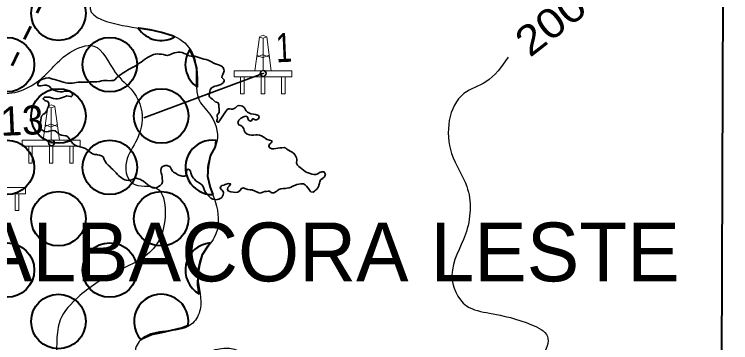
# Model space of a CAD drawing. Extents: x -10.5 to 30.8, y 18.4 to 58.7.
# Drawn here: x 25.827 to 30.756, y 40.973 to 43.233 of the extents above; entities that cross this region are included whole.
import ezdxf
from ezdxf.enums import TextEntityAlignment as Align

# ---------------------------------------------------------------- set-up
doc = ezdxf.new("R2010")
doc.units = 0
doc.header["$LTSCALE"] = 0.08
doc.header["$PDMODE"] = 32
doc.header["$PDSIZE"] = 0.04
doc.linetypes.add('DASH_DOUBLE_DOT', pattern=[9.2, 5, -1.2, 0.3, -1.2, 0.3, -1.2])
doc.layers.add('13', color=7, linetype='Continuous')
for name, color, linetype, lineweight in [('19', 7, 'DASH_DOUBLE_DOT', 53), ('28', 7, 'Continuous', 25), ('36', 7, 'Continuous', 13), ('44', 7, 'Continuous', 35), ('6', 7, 'Continuous', 40), ('60', 7, 'Continuous', 13), ('8', 7, 'Continuous', 25)]:
    doc.layers.add(name, color=color, linetype=linetype, lineweight=lineweight)

msp = doc.modelspace()

# ---------------------------------------------------------------- linework, layer by layer
at = {"layer": '19'}
msp.add_arc((-10.0428, 60.19451), 39.81815, 297.24377, 345.91847, dxfattribs=at)
at = {"layer": '28', "lineweight": 35}
for points in [[(27.09656, 42.93611), (27.08285, 42.94108), (27.06886, 42.9447), (27.05912, 42.94579), (27.0445, 42.94634), (27.03016, 42.94842), (27.02726, 42.94931), (27.01385, 42.95514), (27.00867, 42.95795), (26.99573, 42.96464), (26.98227, 42.96979), (26.968, 42.97204), (26.95325, 42.97191), (26.94302, 42.97062), (26.92882, 42.96748), (26.92765, 42.96709), (26.91402, 42.96246), (26.90053, 42.95664), (26.8934, 42.9538), (26.87937, 42.9505), (26.86785, 42.95169), (26.85343, 42.95562), (26.85325, 42.95578), (26.83888, 42.95853), (26.82441, 42.95976), (26.81325, 42.96046), (26.79877, 42.95983), (26.79752, 42.95961), (26.78341, 42.95613), (26.76981, 42.95082), (26.75678, 42.94402), (26.7478, 42.93908), (26.73548, 42.93146), (26.72335, 42.92334), (26.7218, 42.92227), (26.71003, 42.91366), (26.69834, 42.90506), (26.68665, 42.89646), (26.67461, 42.88818), (26.66936, 42.88475), (26.65705, 42.87696), (26.64455, 42.86967), (26.64289, 42.86893), (26.63013, 42.8618), (26.61736, 42.85484), (26.60468, 42.84788), (26.59209, 42.84059), (26.57978, 42.8328), (26.56863, 42.82524), (26.55694, 42.81681), (26.55302, 42.81377), (26.54168, 42.80501), (26.53071, 42.79543), (26.51976, 42.78534), (26.50947, 42.77748), (26.49559, 42.77688), (26.49466, 42.77684), (26.48008, 42.77654), (26.46566, 42.7766), (26.45871, 42.77748), (26.44414, 42.77887), (26.44254, 42.7788), (26.42824, 42.77599), (26.42625, 42.7754), (26.41252, 42.77109)], [(27.22661, 42.54589), (27.23642, 42.55677), (27.23711, 42.56422), (27.23684, 42.57062), (27.23664, 42.57331), (27.23508, 42.58774), (27.23494, 42.58909), (27.23439, 42.60374), (27.23436, 42.61031), (27.23032, 42.6238), (27.21734, 42.62762), (27.20862, 42.63028), (27.19856, 42.64047), (27.19072, 42.6484), (27.17855, 42.65681), (27.16854, 42.66599), (27.16826, 42.67239), (27.16833, 42.67475), (27.16913, 42.68929), (27.17121, 42.70355), (27.17496, 42.71434), (27.18312, 42.7265), (27.18759, 42.7304), (27.20081, 42.73671), (27.20556, 42.73809), (27.21977, 42.7409), (27.23378, 42.74471), (27.24727, 42.75052), (27.25361, 42.754), (27.26486, 42.76309), (27.27075, 42.77515), (27.27043, 42.78256), (27.26477, 42.78856), (27.25375, 42.79769), (27.25748, 42.81084), (27.2614, 42.81961), (27.26617, 42.83028), (27.26986, 42.84443), (27.26935, 42.85419), (27.26354, 42.86777), (27.25947, 42.87198), (27.24691, 42.8797), (27.23773, 42.88335), (27.22381, 42.88747), (27.2102, 42.89211), (27.20831, 42.89288), (27.19536, 42.89974), (27.18274, 42.90695), (27.17403, 42.9113), (27.16064, 42.91679), (27.14678, 42.92142), (27.14559, 42.9217), (27.13151, 42.92548), (27.11751, 42.92926), (27.10358, 42.93355), (27.09656, 42.93611)], [(26.41252, 42.77109), (26.40918, 42.77027), (26.39482, 42.76881), (26.38015, 42.76868), (26.36546, 42.76906), (26.36403, 42.769), (26.34956, 42.76837), (26.34888, 42.76834), (26.33442, 42.76738), (26.31986, 42.76675), (26.30538, 42.76612), (26.2908, 42.76583), (26.28035, 42.76571), (26.26577, 42.76542), (26.25132, 42.76412), (26.24178, 42.76253), (26.22747, 42.75988), (26.21304, 42.75825), (26.20866, 42.75823), (26.1941, 42.75929), (26.17982, 42.76204), (26.17615, 42.76306), (26.16223, 42.76701), (26.14838, 42.77148), (26.14804, 42.77146), (26.13411, 42.77575), (26.12019, 42.7797), (26.1062, 42.78348), (26.10586, 42.78347), (26.09178, 42.78724), (26.07801, 42.79188), (26.06713, 42.79562), (26.06146, 42.79622), (26.04685, 42.79474), (26.04385, 42.79394), (26.03003, 42.7898), (26.01988, 42.78649), (26.00691, 42.7802), (26.00195, 42.77611), (25.99257, 42.76474), (25.98673, 42.7515), (25.9925, 42.74112), (26.00108, 42.74149), (26.00748, 42.74177), (26.00798, 42.74179), (26.02229, 42.74443), (26.03329, 42.74558), (26.04792, 42.7447), (26.05276, 42.7439), (26.06629, 42.73908), (26.06908, 42.73684), (26.07876, 42.72562), (26.08376, 42.72112), (26.09632, 42.71357), (26.09941, 42.71218), (26.11289, 42.70669)], [(26.11289, 42.70669), (26.12675, 42.70206), (26.12974, 42.70118), (26.14394, 42.69859), (26.15787, 42.7002), (26.16683, 42.7016), (26.18126, 42.70341), (26.18821, 42.70455), (26.20255, 42.70433), (26.21348, 42.6994), (26.22458, 42.69027), (26.22476, 42.68994), (26.22632, 42.67534), (26.22029, 42.66664), (26.21169, 42.66846), (26.19873, 42.66993), (26.18904, 42.6717), (26.18268, 42.67041), (26.17218, 42.66557), (26.17103, 42.66502), (26.15751, 42.65971), (26.15202, 42.65795), (26.13803, 42.65398), (26.12361, 42.65183), (26.11115, 42.65146), (26.0968, 42.65371), (26.09611, 42.65402), (26.08238, 42.6595), (26.06864, 42.66329), (26.06281, 42.66354), (26.04831, 42.66342), (26.0478, 42.66357), (26.03328, 42.66395), (26.02415, 42.65276), (26.03082, 42.64664), (26.03526, 42.6416), (26.03613, 42.6408), (26.04955, 42.6348), (26.05929, 42.63185), (26.06514, 42.61945), (26.06464, 42.60762), (26.06297, 42.60334), (26.0568, 42.59008), (26.05599, 42.58718), (26.05315, 42.57289), (26.05126, 42.56792), (26.04222, 42.55656), (26.03545, 42.55121), (26.02351, 42.54277), (26.0231, 42.54241), (26.01336, 42.5317), (26.01025, 42.52178), (26.00912, 42.50689), (26.00874, 42.50401), (26.00657, 42.48975), (26.00398, 42.47564), (26.00309, 42.46683), (26.00288, 42.45231), (26.00288, 42.45231), (26.00636, 42.44589), (26.01207, 42.43871), (26.01747, 42.43675), (26.01961, 42.43583), (26.03169, 42.42775), (26.03254, 42.42745)], [(27.34897, 42.59081), (27.34953, 42.59134), (27.34317, 42.58635), (27.33405, 42.58275), (27.32757, 42.58044), (27.31966, 42.5801), (27.30953, 42.58236), (27.301, 42.58267), (27.292, 42.57823), (27.2863, 42.57141), (27.28006, 42.56186), (27.2701, 42.54827), (27.25774, 42.52801), (27.23924, 42.49938), (27.23044, 42.49039), (27.23213, 42.4903), (27.23019, 42.49021), (27.21978, 42.49516), (27.2195, 42.50156), (27.22123, 42.51024), (27.22414, 42.51896), (27.22145, 42.53251), (27.22213, 42.54013), (27.22661, 42.54589)], [(27.5998, 42.35997), (27.59789, 42.36309), (27.58242, 42.36782), (27.58183, 42.36796), (27.56729, 42.37256), (27.5552, 42.37929), (27.55137, 42.38199), (27.53938, 42.39008), (27.52658, 42.39745), (27.5138, 42.40246), (27.49953, 42.40471), (27.48741, 42.40419), (27.47289, 42.40255), (27.45849, 42.4021), (27.44391, 42.40383), (27.4299, 42.40811), (27.42576, 42.41013), (27.41449, 42.41925), (27.40978, 42.42866), (27.40882, 42.43149), (27.40484, 42.44548), (27.39736, 42.45848), (27.38569, 42.46709), (27.38534, 42.46724), (27.37149, 42.4717), (27.37053, 42.4725), (27.36356, 42.48536), (27.36357, 42.48721), (27.36931, 42.50062), (27.37217, 42.50462), (27.38252, 42.51502), (27.38759, 42.51861), (27.40374, 42.5274), (27.41951, 42.53129), (27.43008, 42.52669), (27.4309, 42.52537), (27.43507, 42.51088), (27.43827, 42.50512), (27.45065, 42.49772), (27.45998, 42.50235), (27.46586, 42.51441), (27.46948, 42.51473), (27.48437, 42.50779), (27.4936, 42.50683), (27.50662, 42.51398), (27.50678, 42.51415), (27.51132, 42.52801), (27.50565, 42.53637), (27.50026, 42.54001), (27.4865, 42.54431), (27.47159, 42.54586), (27.45706, 42.54826), (27.45408, 42.54898), (27.44067, 42.55498), (27.43214, 42.55899), (27.42088, 42.56795), (27.41666, 42.57569), (27.41036, 42.58892), (27.40805, 42.59151), (27.39597, 42.59993), (27.38728, 42.60394), (27.37326, 42.60637), (27.36179, 42.6025), (27.35032, 42.59273), (27.34897, 42.59081)], [(26.03254, 42.42745), (26.04657, 42.42486), (26.06165, 42.42703), (26.06675, 42.42826), (26.08075, 42.43207), (26.09135, 42.43455), (26.09228, 42.43459), (26.10643, 42.43099), (26.10772, 42.43037), (26.11964, 42.42195), (26.12682, 42.41585), (26.1386, 42.40674), (26.15159, 42.40089), (26.16506, 42.39945), (26.17947, 42.39772), (26.1828, 42.39668), (26.19494, 42.38894), (26.20496, 42.37757), (26.21193, 42.36674), (26.21978, 42.35476), (26.22934, 42.34421), (26.24111, 42.33528), (26.25406, 42.32842), (26.25843, 42.32675), (26.27244, 42.32263), (26.28659, 42.3192), (26.29564, 42.31672), (26.30935, 42.31158), (26.31572, 42.30865), (26.32834, 42.30144), (26.34011, 42.29267), (26.34046, 42.29235), (26.35158, 42.28288), (26.36333, 42.27445), (26.36488, 42.27367), (26.37859, 42.2687), (26.39147, 42.26723), (26.39878, 42.26586), (26.41309, 42.2626), (26.42613, 42.25945), (26.43809, 42.25204), (26.44044, 42.24827), (26.44527, 42.23414), (26.4467, 42.23032), (26.45324, 42.21745), (26.46185, 42.20568), (26.47184, 42.19498), (26.48273, 42.18499), (26.49386, 42.17519), (26.50492, 42.16521), (26.5065, 42.16376), (26.51666, 42.15307), (26.52656, 42.14253), (26.53648, 42.13166), (26.54662, 42.12147), (26.5574, 42.11199)], [(27.92664, 42.07186), (27.92838, 42.08054), (27.93422, 42.09361), (27.93649, 42.09573), (27.94879, 42.10385), (27.94985, 42.10458), (27.96003, 42.11497), (27.96241, 42.11844), (27.9667, 42.13229), (27.96612, 42.13598), (27.95751, 42.14792), (27.95673, 42.14839), (27.94266, 42.15014), (27.92772, 42.1446), (27.92723, 42.14424), (27.91425, 42.13626), (27.90159, 42.13049), (27.88953, 42.13047), (27.87473, 42.13354), (27.86261, 42.1369), (27.84884, 42.14136), (27.83569, 42.14703), (27.82757, 42.15157), (27.81557, 42.15982), (27.80396, 42.16894), (27.7926, 42.17823), (27.7848, 42.18497), (27.77481, 42.19567), (27.76887, 42.20807), (27.7685, 42.21277), (27.77015, 42.22735), (27.77015, 42.23325), (27.76716, 42.24763), (27.76611, 42.25045), (27.7593, 42.26365), (27.75002, 42.27539), (27.73883, 42.28469), (27.73838, 42.28517), (27.72568, 42.29221), (27.71259, 42.29856), (27.70272, 42.30455), (27.6949, 42.3118), (27.68335, 42.31551), (27.66803, 42.31485), (27.65427, 42.31341), (27.64, 42.31178), (27.62558, 42.30981), (27.61292, 42.30808), (27.59774, 42.3081), (27.58478, 42.31328), (27.57792, 42.32377), (27.57771, 42.32478), (27.58157, 42.33894), (27.59185, 42.34681), (27.59697, 42.35125), (27.5998, 42.35997)], [(26.5574, 42.11199), (26.56071, 42.10943), (26.57295, 42.10136), (26.58605, 42.09501), (26.5975, 42.09146), (26.61191, 42.08972), (26.61217, 42.08973), (26.6266, 42.09137), (26.64047, 42.09635), (26.64516, 42.09892), (26.65824, 42.10454), (26.66531, 42.10485), (26.67989, 42.10126), (26.68915, 42.09778), (26.70247, 42.09195), (26.71477, 42.08455), (26.71807, 42.08217), (26.72928, 42.0727), (26.74031, 42.06323), (26.74625, 42.05859), (26.75816, 42.05034), (26.77111, 42.04331), (26.77963, 42.03929), (26.79383, 42.0367), (26.80253, 42.03843), (26.81589, 42.04524), (26.8191, 42.04707), (26.83121, 42.05569), (26.84061, 42.06655), (26.84544, 42.07958), (26.84595, 42.08736), (26.84447, 42.10197), (26.84318, 42.11423), (26.84113, 42.12847), (26.8377, 42.14165), (26.83463, 42.15602), (26.83435, 42.15871), (26.836, 42.17312), (26.83669, 42.17466), (26.84678, 42.18522), (26.86093, 42.1914), (26.86453, 42.19206), (26.87903, 42.19218), (26.88328, 42.19135), (26.89644, 42.18534), (26.90143, 42.17915), (26.90768, 42.16542), (26.91496, 42.15309), (26.9228, 42.14719), (26.93585, 42.13999), (26.94682, 42.13187), (26.95259, 42.12908), (26.96646, 42.12428), (26.96774, 42.124), (26.98159, 42.11954), (26.98507, 42.11901), (26.99978, 42.12032), (27.00918, 42.12512), (27.01083, 42.12806), (27.0116, 42.14327), (27.0122, 42.15291), (27.01488, 42.165), (27.02333, 42.1684), (27.03214, 42.16355), (27.03783, 42.153)], [(27.03783, 42.153), (27.0411, 42.14168), (27.04542, 42.1277), (27.05146, 42.11666), (27.06023, 42.10489), (27.06539, 42.09871), (27.07555, 42.08818), (27.08706, 42.07924), (27.09337, 42.0758), (27.10649, 42.06878), (27.11781, 42.06049), (27.11781, 42.06049), (27.12533, 42.04851), (27.1304, 42.03473), (27.13557, 42.02045), (27.14235, 42.00792), (27.15087, 41.99615), (27.16062, 41.98527), (27.16626, 41.97961), (27.17722, 41.96996), (27.17973, 41.96839), (27.19261, 41.96118), (27.20669, 41.95741), (27.20812, 41.9573), (27.22276, 41.9581), (27.23367, 41.96127), (27.24689, 41.96775), (27.2542, 41.97228), (27.25724, 41.97595), (27.26306, 41.9897), (27.26335, 41.99072), (27.26662, 42.00469), (27.26597, 42.01006), (27.25733, 42.02268), (27.25055, 42.02744), (27.24283, 42.03807), (27.24577, 42.04242), (27.25284, 42.05234), (27.25547, 42.05397), (27.2697, 42.05829), (27.27162, 42.05888), (27.28446, 42.06416), (27.29921, 42.06834), (27.30005, 42.06838), (27.31433, 42.06562), (27.31453, 42.0631), (27.30421, 42.05017), (27.29637, 42.04039), (27.29348, 42.02728), (27.30147, 42.01598), (27.30173, 42.01583), (27.31551, 42.01119), (27.31923, 42.01085), (27.33378, 42.00996), (27.33471, 42.00983), (27.35018, 42.00696)], [(27.35018, 42.00696), (27.36376, 42.0089), (27.37311, 42.01706), (27.38353, 42.02375), (27.38833, 42.03357), (27.38978, 42.03515), (27.40422, 42.03864), (27.41291, 42.03463), (27.41936, 42.03171), (27.43351, 42.0281), (27.43589, 42.0277), (27.45047, 42.02614), (27.46464, 42.02405), (27.46609, 42.02361), (27.47953, 42.01913), (27.49305, 42.01246), (27.49556, 42.01105), (27.5096, 42.00424), (27.52331, 42.00315), (27.52398, 42.00334), (27.53692, 42.01014), (27.54785, 42.01298), (27.56246, 42.01445), (27.57403, 42.01597), (27.58156, 42.01528), (27.58216, 42.01514), (27.59376, 42.00619), (27.59824, 42.00419), (27.61305, 42.00483), (27.61637, 42.00616), (27.62867, 42.01411), (27.63463, 42.01859), (27.64683, 42.02704), (27.66001, 42.0325), (27.66276, 42.03313), (27.67732, 42.03376), (27.69199, 42.03389), (27.7012, 42.03546), (27.71529, 42.03911), (27.71721, 42.0397), (27.7311, 42.04418), (27.73425, 42.0455), (27.74728, 42.05213), (27.76043, 42.05827), (27.76966, 42.06119), (27.78379, 42.064), (27.79862, 42.06633), (27.80013, 42.06656), (27.81461, 42.06702), (27.81538, 42.06671), (27.82769, 42.05898), (27.83633, 42.05042), (27.84574, 42.03952), (27.84619, 42.03887), (27.85479, 42.0271), (27.86271, 42.01563), (27.86767, 42.01214), (27.88218, 42.01007), (27.89267, 42.01693), (27.89618, 42.01978), (27.90715, 42.02936), (27.91457, 42.03913), (27.92108, 42.05239), (27.92296, 42.0577), (27.92664, 42.07186)]]:
    msp.add_lwpolyline(points, dxfattribs=at)
at = {"layer": '36'}
for p, q in [((27.53849, 43.08867), (27.51518, 43.07956)), ((27.53849, 43.08867), (27.56292, 43.0791)), ((27.48219, 42.84435), (27.51467, 43.07676)), ((27.53849, 43.06811), (27.51467, 43.07676)), ((27.53849, 43.06811), (27.56333, 43.07722)), ((27.53849, 42.84435), (27.53849, 43.06811)), ((27.59489, 42.84435), (27.56333, 43.07722)), ((27.53849, 42.95598), (27.49563, 42.93933)), ((27.53849, 42.93455), (27.49696, 42.95028)), ((27.53849, 42.95506), (27.58196, 42.93882)), ((27.53849, 42.93597), (27.58053, 42.9517)), ((26.02483, 42.36677), (26.05731, 42.59918)), ((26.08113, 42.59053), (26.05731, 42.59918)), ((26.08113, 42.61109), (26.05782, 42.60198)), ((26.08113, 42.61109), (26.10556, 42.60152)), ((26.08113, 42.59053), (26.10597, 42.59964)), ((26.08113, 42.36677), (26.08113, 42.59053)), ((26.13753, 42.36677), (26.10597, 42.59964)), ((26.08113, 42.4784), (26.03827, 42.46175)), ((26.08113, 42.45697), (26.03959, 42.47269)), ((26.08113, 42.47748), (26.1246, 42.46124)), ((26.08113, 42.45839), (26.12317, 42.47412))]:
    msp.add_line(p, q, dxfattribs=at)
at = {"layer": '36', "lineweight": 35}
msp.add_line((26.71859, 42.52113), (27.53706, 42.82572), dxfattribs=at)
at = {"layer": '36'}
for points in [[(27.33855, 42.84435), (27.73659, 42.84435), (27.73659, 42.80282), (27.33855, 42.80282)], [(27.38345, 42.80282), (27.40778, 42.80282), (27.40778, 42.68687), (27.38345, 42.68687)], [(27.52515, 42.80282), (27.54948, 42.80282), (27.54948, 42.68687), (27.52515, 42.68687)], [(27.66543, 42.80282), (27.68987, 42.80282), (27.68987, 42.68687), (27.66543, 42.68687)], [(25.88119, 42.36677), (26.27923, 42.36677), (26.27923, 42.32524), (25.88119, 42.32524)], [(25.92609, 42.32524), (25.95042, 42.32524), (25.95042, 42.20929), (25.92609, 42.20929)], [(26.06779, 42.32524), (26.09212, 42.32524), (26.09212, 42.20929), (26.06779, 42.20929)], [(26.20807, 42.32524), (26.23251, 42.32524), (26.23251, 42.20929), (26.20807, 42.20929)], [(25.50643, 42.04002), (25.90447, 42.04002), (25.90447, 41.99849), (25.50643, 41.99849)], [(25.83331, 41.99849), (25.85774, 41.99849), (25.85774, 41.88254), (25.83331, 41.88254)]]:
    msp.add_lwpolyline(points, close=True, dxfattribs=at)
for p in [(27.53706, 42.82572), (27.54185, 42.82715), (26.0797, 42.34814), (26.08449, 42.34957)]:
    msp.add_point(p, dxfattribs=at)
at = {"layer": '44'}
msp.add_lwpolyline([(-6.64608, 21.84641), (-6.71324, 21.73), (30.62637, 21.73), (30.75566, 58.74412)], dxfattribs=at)
at = {"layer": '6'}
for points in [[(26.92965, 43.07725), (26.91468, 43.08473), (26.83832, 43.10769), (26.7617, 43.12665), (26.68386, 43.13796), (26.67971, 43.13859)], [(27.08659, 42.73089), (27.08674, 42.78905), (27.08352, 42.86172), (27.06335, 42.93027), (27.03467, 42.99073)], [(27.19449, 41.99224), (27.17314, 42.04734), (27.15919, 42.11609), (27.1623, 42.1876), (27.17585, 42.25831), (27.2105, 42.32171), (27.21488, 42.36564)], [(27.09899, 41.30908), (27.09035, 41.36909), (27.09174, 41.43991), (27.10337, 41.51008), (27.12234, 41.57942), (27.16057, 41.63965), (27.17477, 41.65942)], [(26.69848, 40.99288), (26.70288, 40.99968), (26.76964, 41.02992), (26.83938, 41.04307), (26.90849, 41.05871), (26.97676, 41.07588), (27.02298, 41.09383)]]:
    msp.add_lwpolyline(points, dxfattribs=at)
for centre in [(26.13008, 43.24037), (25.77652, 42.88681), (26.48363, 42.88681), (26.13008, 42.53326), (26.83718, 42.53326), (25.77652, 42.17971), (26.48363, 42.17971), (26.13008, 41.82615), (26.83718, 41.82615), (25.77652, 41.4726), (26.48363, 41.4726), (26.13008, 41.11904)]:
    msp.add_circle(centre, 0.1875, dxfattribs=at)
for centre, start, end in [((26.83718, 43.24037), 212.8735, 299.54745), ((27.19074, 42.88681), 146.34295, 236.26025), ((27.19074, 42.17971), 82.60112, 271.1456), ((27.19074, 41.4726), 94.88496, 240.70367), ((26.83718, 41.11904), 352.27116, 222.28885)]:
    msp.add_arc(centre, 0.1875, start, end, dxfattribs=at)
at = {"layer": '6', "lineweight": 25}
msp.add_spline([(25.36052, 48.15187), (25.37063, 48.13594), (25.45676, 48.00839), (25.66927, 47.88356), (25.81587, 47.85442), (25.92468, 47.78934), (26.02537, 47.61431), (26.06046, 47.34623), (26.1638, 47.07154), (26.27111, 46.94881), (26.44749, 46.85092), (26.51176, 46.69235), (26.67625, 46.54227), (26.80432, 46.40864), (26.87358, 46.23949), (26.89358, 45.99792), (26.83175, 45.84711), (26.77354, 45.63331), (26.86316, 45.43754), (26.88965, 45.24303), (26.80303, 45.15039), (26.73977, 45.14641), (26.68416, 45.03217), (26.77473, 44.87308), (26.92371, 44.73379), (26.9567, 44.58633), (27.1414, 44.40439), (27.1459, 44.17362), (26.99008, 44.0509), (26.95285, 44.03591), (26.91937, 43.96318), (26.88165, 43.72801), (26.77303, 43.5991), (26.61236, 43.49221), (26.43119, 43.40669), (26.34874, 43.27203), (26.57204, 43.15747), (26.80778, 43.11607), (26.98497, 43.04962), (27.07083, 42.91159), (27.10053, 42.63837), (27.18195, 42.53188), (27.21357, 42.33203), (27.1747, 42.25416), (27.16021, 42.10241), (27.2184, 41.9125), (27.20227, 41.69787), (27.12575, 41.5893), (27.08981, 41.42224), (27.1051, 41.20174), (27.0553, 41.10836), (26.89073, 41.05397), (26.72658, 41.0153), (26.66128, 40.93272), (26.71544, 40.79009), (26.95835, 40.82194), (27.17121, 40.91206), (27.28236, 40.93606), (27.37123, 40.91331), (27.39651, 40.71409)], degree=3, dxfattribs=at)
at = {"layer": '60', "lineweight": 40}
msp.add_line((30.75566, 58.74412), (30.62637, 21.73), dxfattribs=at)
msp.add_line((30.75566, 58.74412), (30.62637, 21.73), dxfattribs=at)
at = {"layer": '8'}
for points in [[(25.36052, 48.15187), (25.37063, 48.13594), (25.45676, 48.00839), (25.66927, 47.88356), (25.81587, 47.85442), (25.92468, 47.78934), (26.02537, 47.61431), (26.06046, 47.34623), (26.1638, 47.07154), (26.27111, 46.94881), (26.44749, 46.85092), (26.51176, 46.69235), (26.67625, 46.54227), (26.80432, 46.40864), (26.87358, 46.23949), (26.89358, 45.99792), (26.83175, 45.84711), (26.77354, 45.63331), (26.86316, 45.43754), (26.88965, 45.24303), (26.80303, 45.15039), (26.73977, 45.14641), (26.68416, 45.03217), (26.77473, 44.87308), (26.92371, 44.73379), (26.9567, 44.58633), (27.1414, 44.40439), (27.1459, 44.17362), (26.99008, 44.0509), (26.95285, 44.03591), (26.91937, 43.96318), (26.88165, 43.72801), (26.77303, 43.5991), (26.61236, 43.49221), (26.43119, 43.40669), (26.34874, 43.27203), (26.57204, 43.15747), (26.80778, 43.11607), (26.98497, 43.04962), (27.07083, 42.91159), (27.10053, 42.63837), (27.18195, 42.53188), (27.21357, 42.33203), (27.1747, 42.25416), (27.16021, 42.10241), (27.2184, 41.9125), (27.20227, 41.69787), (27.12575, 41.5893), (27.08981, 41.42224), (27.1051, 41.20174), (27.0553, 41.10836), (26.89073, 41.05397), (26.72658, 41.0153), (26.66128, 40.93272), (26.71544, 40.79009), (26.95835, 40.82194), (27.17121, 40.91206), (27.28236, 40.93606), (27.37123, 40.91331), (27.39651, 40.71409)], [(25.74246, 45.64865), (25.74723, 45.42835), (25.72556, 45.20335), (25.77945, 45.05022), (25.91498, 45.00034), (26.04497, 44.94007), (26.10357, 44.76589), (26.24408, 44.70541), (26.38432, 44.63445), (26.37981, 44.46153), (26.30677, 44.28473), (26.29051, 44.06486), (26.15238, 44.01519), (25.93911, 43.90934), (25.76197, 43.77656), (25.66913, 43.64735), (25.65689, 43.38021), (25.59062, 43.26094), (25.55331, 43.04149), (25.59934, 42.78891), (25.69709, 42.70307), (25.9937, 42.7758), (26.2093, 42.97073), (26.37359, 43.01463), (26.52147, 42.83342), (26.64428, 42.6999), (26.70385, 42.5624), (26.66155, 42.35353), (26.59433, 42.19759), (26.63838, 42.07088), (26.80587, 42.03608), (26.86475, 41.87237), (26.78454, 41.62232), (26.50637, 41.44961), (26.24911, 41.27125), (26.13427, 41.10577), (26.12832, 41.07967), (26.11027, 40.79168), (26.09595, 40.71409)], [(29.22407, 42.93739), (29.07098, 42.76802), (28.92033, 42.68759), (28.83476, 42.27597), (28.9398, 42.04859), (28.93071, 41.71904), (28.83815, 41.43843), (28.93833, 41.22686), (29.09596, 41.17629), (29.38531, 41.09665), (29.49439, 41.01574), (29.45899, 40.88567), (29.16975, 40.77687), (28.93593, 40.71409)]]:
    msp.add_spline(points, degree=3, dxfattribs=at)

# ---------------------------------------------------------------- texts
at = {"layer": '13'}
msp.add_text('ALBACORA LESTE', height=0.405, dxfattribs=at).set_placement((27.99772, 41.39495), align=Align.CENTER)
at = {"layer": '36', "width": 0.75}
msp.add_text('1', height=0.2, rotation=2.479, dxfattribs=at).set_placement((27.62983, 42.90252))
at = {"layer": '36'}
msp.add_text('13', height=0.2, rotation=2.479, dxfattribs=at).set_placement((25.73436, 42.39611))
at = {"layer": '8', "width": 1.15}
msp.add_text('2000', height=0.2032, rotation=37.944, dxfattribs=at).set_placement((29.37413, 42.93163))

doc.saveas('drawing.dxf')
